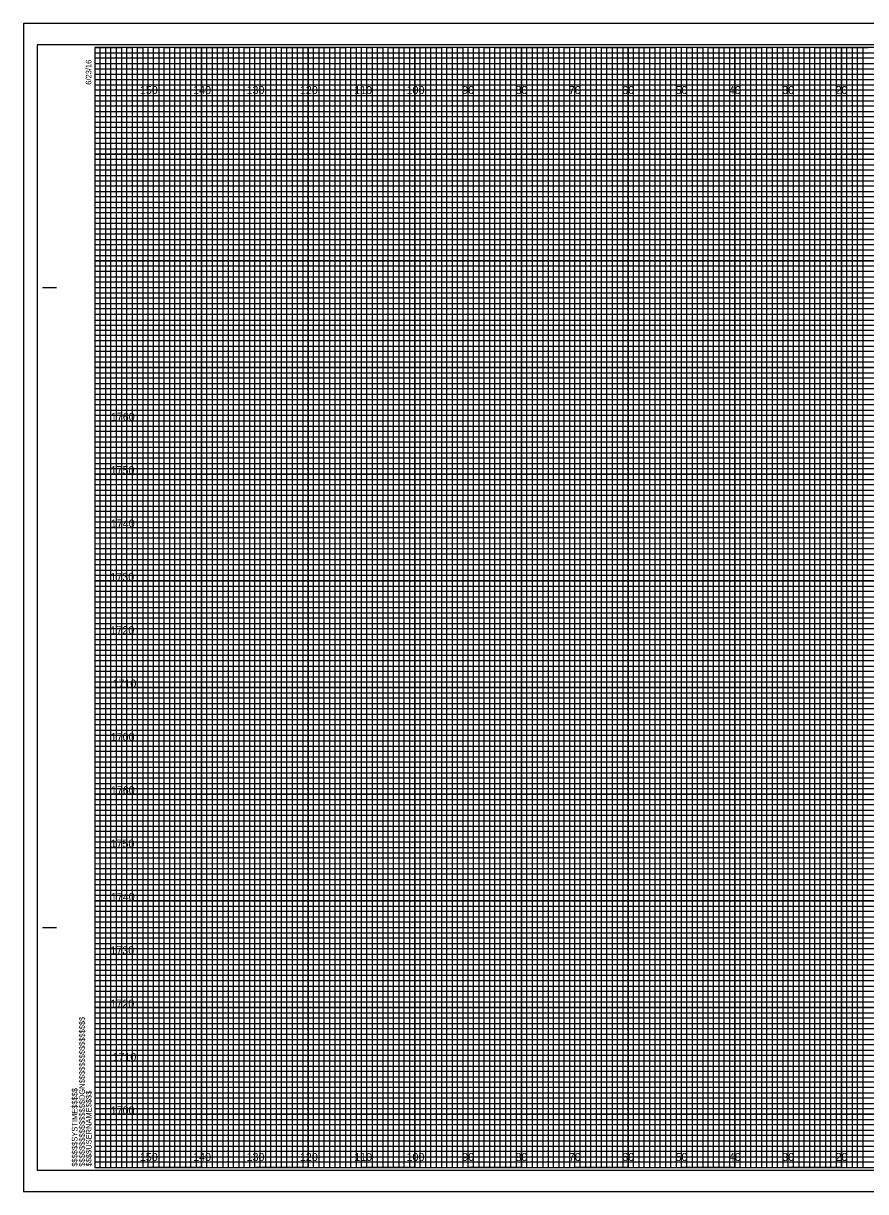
# Model space of a CAD drawing. Extents: x -419 to 4739, y -630 to 13534.
# Drawn here: x 476.2 to 634.1, y 5048 to 5267 of the extents above; entities that cross this region are included whole.
import ezdxf

# ---------------------------------------------------------------- set-up
doc = ezdxf.new("R2010")
doc.units = 0
for name, color, linetype in [('Old_Level_62', 7, 'Continuous'), ('Pattern 1', 7, 'Continuous'), ('Pattern 18', 7, 'Continuous'), ('Pattern 4', 7, 'Continuous'), ('Pattern 5', 7, 'Continuous'), ('Prop Dimension', 7, 'Continuous'), ('Prop Horizontal Alignment', 7, 'Continuous'), ('Raster_Level_0', 7, 'Continuous'), ('Scratch_Level_0', 7, 'Continuous'), ('Scratch_Level_3', 7, 'Continuous'), ('Scratch_Level_5', 7, 'Continuous')]:
    doc.layers.add(name, color=color, linetype=linetype)

msp = doc.modelspace()

# ---------------------------------------------------------------- linework, layer by layer
at = {"layer": 'Old_Level_62'}
for p, q in [((479.78, 5217.54), (482.28, 5217.54)), ((479.88, 5217.54), (482.38, 5217.54)), ((479.78, 5097.54), (482.28, 5097.54)), ((479.88, 5097.54), (482.38, 5097.54)), ((489.58, 5052.54), (489.58, 5052.54)), ((489.58, 5052.54), (489.58, 5052.54)), ((489.58, 5052.54), (489.58, 5052.54)), ((489.58, 5052.54), (489.58, 5052.54)), ((489.58, 5052.54), (489.58, 5052.54)), ((489.58, 5052.54), (489.58, 5052.54)), ((489.58, 5052.54), (489.58, 5052.54))]:
    msp.add_line(p, q, dxfattribs=at)
msp.add_lwpolyline([(809.58, 5262.54), (489.58, 5262.54), (489.58, 5052.54), (809.58, 5052.54)], close=True, dxfattribs=at)
at = {"layer": 'Pattern 18'}
msp.add_lwpolyline([(476.18, 5048.04), (812.88, 5048.04), (812.88, 5267.04), (476.18, 5267.04)], close=True, dxfattribs=at)
at = {"layer": 'Pattern 4'}
for p, q in [((489.58, 5261.54), (749.58, 5261.54)), ((749.58, 5260.52), (489.58, 5260.52)), ((489.58, 5260.52), (489.58, 5259.54)), ((489.58, 5259.54), (749.58, 5259.54)), ((749.58, 5258.43), (489.58, 5258.43)), ((489.58, 5258.43), (489.58, 5256.54)), ((489.58, 5256.54), (809.58, 5256.54))]:
    msp.add_line(p, q, dxfattribs=at)
for points in [[(489.58, 5255.54), (759.58, 5255.54), (809.58, 5255.54), (809.58, 5254.54), (489.58, 5254.54)], [(489.58, 5253.54), (809.58, 5253.54), (809.58, 5251.54), (489.58, 5251.54)], [(489.58, 5250.54), (809.58, 5250.54), (809.58, 5249.54), (489.58, 5249.52)], [(489.58, 5248.54), (809.58, 5248.54), (809.58, 5246.54), (489.58, 5246.54)], [(489.58, 5245.54), (809.58, 5245.54), (809.58, 5244.54), (489.58, 5244.54)], [(489.58, 5243.54), (809.58, 5243.54), (809.58, 5241.54), (489.58, 5241.54)], [(489.58, 5240.54), (809.58, 5240.54), (809.58, 5239.54), (489.58, 5239.54)], [(489.58, 5238.54), (809.58, 5238.54), (809.58, 5236.54), (489.58, 5236.54)], [(489.58, 5235.54), (809.58, 5235.54), (809.58, 5234.54), (489.58, 5234.54)], [(489.58, 5233.54), (809.58, 5233.54), (809.58, 5231.54), (489.58, 5231.54)], [(489.58, 5230.54), (809.58, 5230.54), (809.58, 5229.54), (489.58, 5229.54)], [(489.58, 5228.54), (809.58, 5228.54), (809.58, 5226.49), (809.58, 5225.54), (809.58, 5224.54), (489.58, 5224.54)], [(489.58, 5226.54), (809.58, 5226.54), (809.58, 5225.54), (489.58, 5225.54)], [(489.58, 5223.54), (809.58, 5223.54), (809.58, 5221.54), (489.58, 5221.57)], [(489.58, 5221.57), (809.58, 5221.54), (809.58, 5220.54), (489.58, 5220.54)], [(489.58, 5219.54), (809.58, 5219.54), (809.58, 5218.54), (489.58, 5218.54)], [(489.58, 5216.54), (809.58, 5216.54), (809.58, 5215.54), (489.58, 5215.54)], [(489.58, 5214.54), (809.58, 5214.54), (809.58, 5213.54), (489.58, 5213.54)], [(489.51, 5211.43), (809.58, 5211.43), (809.58, 5210.42), (489.51, 5210.42)], [(489.58, 5209.54), (809.58, 5209.54), (809.58, 5208.54), (489.58, 5208.54)], [(489.58, 5206.54), (809.58, 5206.54), (809.58, 5205.54), (489.58, 5205.54)], [(489.58, 5204.54), (809.58, 5204.54), (809.58, 5203.54), (489.58, 5203.54)], [(489.58, 5201.54), (809.58, 5201.54), (809.58, 5200.54), (489.58, 5200.54)], [(489.58, 5199.54), (809.58, 5199.54), (809.58, 5198.54), (489.58, 5198.54)], [(489.58, 5196.54), (809.58, 5196.54), (809.58, 5195.54), (489.58, 5195.54)], [(489.58, 5194.54), (809.58, 5194.54), (809.58, 5193.54), (489.58, 5193.54)], [(489.58, 5191.54), (809.58, 5191.54), (809.57, 5190.52), (489.58, 5190.54)], [(489.58, 5189.54), (809.58, 5189.54), (809.58, 5188.54), (489.58, 5188.54)], [(489.58, 5186.54), (809.58, 5186.54), (809.58, 5185.54), (489.58, 5185.54)], [(489.58, 5184.54), (809.58, 5184.54), (809.58, 5183.54), (489.58, 5183.54)], [(489.58, 5181.54), (809.58, 5181.54), (809.58, 5180.54), (489.58, 5180.54)], [(489.58, 5179.54), (809.58, 5179.54), (809.58, 5178.54), (489.58, 5178.54)], [(489.58, 5176.54), (809.58, 5176.54), (809.58, 5175.54), (489.58, 5175.54)], [(489.58, 5174.54), (809.58, 5174.54), (809.58, 5173.54), (489.58, 5173.54)], [(489.58, 5171.54), (809.58, 5171.54), (809.58, 5170.54), (489.58, 5170.54)], [(489.58, 5169.53), (809.65, 5169.45), (809.58, 5168.54), (489.58, 5168.54)], [(489.58, 5166.54), (809.58, 5166.54), (809.58, 5165.54), (489.58, 5165.54)], [(489.58, 5164.54), (809.58, 5164.54), (809.58, 5163.54), (489.58, 5163.54)], [(489.58, 5161.54), (809.58, 5161.54), (809.58, 5160.54), (489.58, 5160.54)], [(489.58, 5159.54), (809.58, 5159.54), (809.58, 5158.54), (489.58, 5158.54)], [(489.58, 5156.54), (809.58, 5156.54), (809.58, 5155.54), (489.58, 5155.54)], [(489.58, 5154.54), (809.58, 5154.54), (809.58, 5153.54), (489.58, 5153.54)], [(489.58, 5151.54), (809.58, 5151.54), (809.58, 5150.54), (489.58, 5150.54)], [(489.58, 5149.54), (809.58, 5149.54), (809.58, 5148.54), (489.58, 5148.54)], [(489.58, 5146.54), (809.58, 5146.54), (809.58, 5145.54), (489.58, 5145.54)], [(489.58, 5144.54), (809.58, 5144.54), (809.58, 5143.54), (489.58, 5143.54)], [(489.58, 5141.54), (809.58, 5141.54), (809.58, 5140.54), (489.58, 5140.54)], [(489.58, 5139.54), (809.58, 5139.54), (809.58, 5138.54), (489.58, 5138.54)], [(489.58, 5136.54), (809.58, 5136.54), (809.58, 5135.54), (489.58, 5135.54)], [(489.58, 5134.54), (809.58, 5134.54), (809.58, 5133.54), (489.58, 5133.54)], [(489.58, 5131.54), (809.58, 5131.54), (809.57, 5130.52), (489.58, 5130.54)], [(489.58, 5129.54), (809.58, 5129.54), (809.58, 5128.54), (489.58, 5128.54)], [(489.58, 5126.54), (809.58, 5126.54), (809.58, 5125.54), (489.58, 5125.54)], [(489.58, 5124.54), (809.58, 5124.54), (809.58, 5123.54), (489.58, 5123.54)], [(489.58, 5121.54), (809.58, 5121.54), (809.58, 5120.54), (489.58, 5120.54)], [(489.58, 5119.54), (809.58, 5119.54), (809.58, 5118.54), (489.58, 5118.54)], [(489.58, 5116.54), (809.58, 5116.54), (809.58, 5115.54), (489.58, 5115.54)], [(489.58, 5114.54), (809.58, 5114.54), (809.58, 5113.54), (489.58, 5113.54)], [(489.58, 5111.54), (809.58, 5111.54), (809.58, 5110.54), (489.58, 5110.54)], [(489.58, 5109.53), (809.65, 5109.45), (809.58, 5108.54), (489.58, 5108.54)], [(489.58, 5106.54), (809.58, 5106.54), (809.58, 5105.54), (489.58, 5105.54)], [(489.58, 5104.54), (809.58, 5104.54), (809.58, 5103.54), (489.58, 5103.54)], [(489.58, 5101.54), (809.58, 5101.54), (809.58, 5100.54), (489.58, 5100.54)], [(489.58, 5099.54), (809.58, 5099.54), (809.58, 5098.54), (489.58, 5098.54)], [(489.58, 5096.54), (809.58, 5096.54), (809.58, 5095.54), (489.58, 5095.54)], [(489.58, 5094.54), (809.58, 5094.54), (809.58, 5093.54), (489.58, 5093.54)], [(489.58, 5091.54), (809.58, 5091.54), (809.58, 5090.54), (489.58, 5090.54)], [(489.58, 5089.54), (809.58, 5089.54), (809.58, 5088.54), (489.58, 5088.54)], [(489.58, 5086.54), (809.58, 5086.54), (809.58, 5085.54), (489.58, 5085.54)], [(489.58, 5084.54), (809.58, 5084.54), (809.58, 5083.54), (489.58, 5083.54)], [(489.58, 5081.54), (809.58, 5081.54), (809.58, 5080.54), (489.58, 5080.54)], [(489.58, 5079.54), (809.58, 5079.54), (809.58, 5078.54), (489.58, 5078.54)], [(489.58, 5076.54), (809.58, 5076.54), (809.58, 5075.54), (489.58, 5075.54)], [(489.58, 5074.54), (809.58, 5074.54), (809.58, 5073.54), (489.58, 5073.54)], [(489.58, 5071.54), (809.58, 5071.54), (809.58, 5070.54), (489.58, 5070.54)], [(489.58, 5069.54), (809.58, 5069.54), (809.58, 5068.54), (489.58, 5068.54)], [(489.58, 5066.54), (809.58, 5066.54), (809.58, 5065.54), (489.58, 5065.54)], [(489.58, 5064.54), (809.58, 5064.54), (809.58, 5063.54), (489.58, 5063.54)], [(489.58, 5061.54), (809.58, 5061.54), (809.58, 5060.54), (489.58, 5060.54)], [(489.58, 5059.54), (809.58, 5059.54), (809.58, 5058.54), (489.58, 5058.54)], [(489.58, 5056.54), (809.58, 5056.54), (809.58, 5055.54), (489.58, 5055.54)], [(489.58, 5054.54), (809.58, 5054.54), (809.58, 5053.54), (489.58, 5053.54)]]:
    msp.add_lwpolyline(points, dxfattribs=at)
at = {"layer": 'Pattern 5'}
for p, q in [((812.88, 5267.04), (476.18, 5267.04)), ((476.18, 5267.04), (476.18, 5048.04)), ((476.18, 5048.04), (812.88, 5048.04))]:
    msp.add_line(p, q, dxfattribs=at)
at = {"layer": 'Prop Dimension'}
for points in [[(489.58, 5052.54), (490.58, 5052.54), (490.58, 5262.54), (491.58, 5262.54), (491.58, 5052.54)], [(491.58, 5052.54), (492.58, 5052.54), (492.58, 5262.54), (493.58, 5262.54), (493.58, 5052.54)], [(494.58, 5052.54), (495.58, 5052.54), (495.58, 5262.54), (496.58, 5262.54), (496.58, 5052.54)], [(496.58, 5052.54), (497.58, 5052.54), (497.58, 5262.54), (498.58, 5262.54), (498.58, 5052.54)], [(499.58, 5052.54), (500.58, 5052.54), (500.58, 5262.54), (501.58, 5262.54), (501.58, 5052.54)], [(501.58, 5052.54), (502.58, 5052.54), (502.58, 5262.54), (503.58, 5262.54), (503.58, 5052.54)], [(504.58, 5052.54), (505.58, 5052.54), (505.58, 5262.54), (506.58, 5262.54), (506.58, 5052.54)], [(506.58, 5052.54), (507.58, 5052.54), (507.58, 5262.54), (508.58, 5262.54), (508.58, 5052.54)], [(509.58, 5052.54), (510.58, 5052.54), (510.58, 5262.54), (511.58, 5262.54), (511.58, 5052.54)], [(511.58, 5052.54), (512.58, 5052.54), (512.58, 5262.54), (513.58, 5262.54), (513.58, 5052.54)], [(514.58, 5052.54), (515.58, 5052.54), (515.58, 5262.54), (516.58, 5262.54), (516.58, 5052.54)], [(516.58, 5052.54), (517.58, 5052.54), (517.58, 5262.54), (518.58, 5262.54), (518.58, 5052.54)], [(519.58, 5052.54), (520.58, 5052.54), (520.58, 5262.54), (521.58, 5262.54), (521.58, 5052.54)], [(521.58, 5052.54), (522.58, 5052.54), (522.58, 5262.54), (523.58, 5262.54), (523.58, 5052.54)], [(524.58, 5052.54), (525.58, 5052.54), (525.58, 5262.54), (526.58, 5262.54), (526.58, 5052.54)], [(526.58, 5052.54), (527.58, 5052.54), (527.58, 5262.54), (528.58, 5262.54), (528.58, 5052.54)], [(529.58, 5052.54), (530.58, 5052.54), (530.58, 5262.54), (531.58, 5262.54), (531.58, 5052.54)], [(531.58, 5052.54), (532.58, 5052.54), (532.58, 5262.54), (533.58, 5262.54), (533.58, 5052.54)], [(534.58, 5052.54), (535.58, 5052.54), (535.58, 5262.54), (536.58, 5262.54), (536.58, 5052.54)], [(536.58, 5052.54), (537.58, 5052.54), (537.58, 5262.54), (538.58, 5262.54), (538.58, 5052.54)], [(539.58, 5052.54), (540.58, 5052.54), (540.58, 5262.54), (541.58, 5262.54), (541.58, 5052.54)], [(541.58, 5052.54), (542.58, 5052.54), (542.58, 5262.54), (543.58, 5262.54), (543.58, 5052.54)], [(544.58, 5052.54), (545.58, 5052.54), (545.58, 5262.54), (546.58, 5262.54), (546.58, 5052.54)], [(546.58, 5052.54), (547.58, 5052.54), (547.58, 5262.54), (548.58, 5262.54), (548.58, 5052.54)], [(549.58, 5052.54), (550.58, 5052.54), (550.58, 5262.54), (551.58, 5262.54), (551.58, 5052.54)], [(551.58, 5052.54), (552.58, 5052.54), (552.58, 5262.54), (553.58, 5262.54), (553.58, 5052.54)], [(554.58, 5052.54), (555.58, 5052.54), (555.58, 5262.54), (556.58, 5262.54), (556.58, 5052.54)], [(556.58, 5052.54), (557.58, 5052.54), (557.58, 5262.54), (558.58, 5262.54), (558.58, 5052.54)], [(559.58, 5052.54), (560.58, 5052.54), (560.58, 5262.54), (561.58, 5262.54), (561.58, 5052.54)], [(561.58, 5052.54), (562.58, 5052.54), (562.58, 5262.54), (563.58, 5262.54), (563.58, 5052.54)], [(564.58, 5052.54), (565.58, 5052.54), (565.58, 5262.54), (566.58, 5262.54), (566.58, 5052.54)], [(566.58, 5052.54), (567.58, 5052.54), (567.58, 5262.54), (568.58, 5262.54), (568.58, 5052.54)], [(569.58, 5052.54), (570.58, 5052.54), (570.58, 5262.54), (571.58, 5262.54), (571.58, 5052.54)], [(571.58, 5052.54), (572.58, 5052.54), (572.58, 5262.54), (573.58, 5262.54), (573.58, 5052.54)], [(574.58, 5052.54), (575.58, 5052.54), (575.58, 5262.54), (576.58, 5262.54), (576.58, 5052.54)], [(576.58, 5052.54), (577.58, 5052.54), (577.58, 5262.54), (578.58, 5262.54), (578.58, 5052.54)], [(579.58, 5052.54), (580.58, 5052.54), (580.58, 5262.54), (581.58, 5262.54), (581.58, 5052.54)], [(581.58, 5052.54), (582.58, 5052.54), (582.58, 5262.54), (583.58, 5262.54), (583.58, 5052.54)], [(584.58, 5052.54), (585.58, 5052.54), (585.58, 5262.54), (586.58, 5262.54), (586.58, 5052.54)], [(586.58, 5052.54), (587.58, 5052.54), (587.58, 5262.54), (588.58, 5262.54), (588.58, 5052.54)], [(589.58, 5052.54), (590.58, 5052.54), (590.58, 5262.54), (591.58, 5262.54), (591.58, 5052.54)], [(591.58, 5052.54), (592.58, 5052.54), (592.58, 5262.54), (593.58, 5262.54), (593.58, 5052.54)], [(594.58, 5052.54), (595.58, 5052.54), (595.58, 5262.54), (596.58, 5262.54), (596.58, 5052.54)], [(596.58, 5052.54), (597.58, 5052.54), (597.58, 5262.54), (598.58, 5262.54), (598.58, 5052.54)], [(599.58, 5052.54), (600.58, 5052.54), (600.58, 5262.54), (601.58, 5262.54), (601.58, 5052.54)], [(601.58, 5052.54), (602.58, 5052.54), (602.58, 5262.54), (603.58, 5262.54), (603.58, 5052.54)], [(604.58, 5052.54), (605.58, 5052.54), (605.58, 5262.54), (606.58, 5262.54), (606.58, 5052.54)], [(606.58, 5052.54), (607.58, 5052.54), (607.58, 5262.54), (608.58, 5262.54), (608.58, 5052.54)], [(609.58, 5052.54), (610.58, 5052.54), (610.58, 5262.54), (611.58, 5262.54), (611.58, 5052.54)], [(611.58, 5052.54), (612.58, 5052.54), (612.58, 5262.54), (613.58, 5262.54), (613.58, 5052.54)], [(614.58, 5052.54), (615.58, 5052.54), (615.58, 5262.54), (616.58, 5262.54), (616.58, 5052.54)], [(616.58, 5052.54), (617.58, 5052.54), (617.58, 5262.54), (618.58, 5262.54), (618.58, 5052.54)], [(619.58, 5052.54), (620.58, 5052.54), (620.58, 5262.54), (621.58, 5262.54), (621.58, 5052.54)], [(621.58, 5052.54), (622.58, 5052.54), (622.58, 5262.54), (623.58, 5262.54), (623.58, 5052.54)], [(624.58, 5052.54), (625.58, 5052.54), (625.58, 5262.54), (626.58, 5262.54), (626.58, 5052.54)], [(626.58, 5052.54), (627.58, 5052.54), (627.58, 5262.54), (628.58, 5262.54), (628.58, 5052.54)], [(629.58, 5052.54), (630.58, 5052.54), (630.58, 5262.54), (631.58, 5262.54), (631.58, 5052.54)], [(631.58, 5052.54), (632.58, 5052.54), (632.58, 5262.54), (633.58, 5262.54), (633.58, 5052.54)]]:
    msp.add_lwpolyline(points, dxfattribs=at)
at = {"layer": 'Prop Horizontal Alignment'}
for points in [[(489.58, 5262.54), (494.58, 5262.54), (494.58, 5052.54), (504.58, 5052.54), (504.58, 5262.54), (514.58, 5262.54), (514.58, 5052.54), (524.58, 5052.54), (524.58, 5262.54), (534.58, 5262.54), (534.58, 5052.54), (544.58, 5052.54), (544.58, 5262.54), (554.58, 5262.54), (554.58, 5052.54), (564.58, 5052.54), (564.58, 5262.54), (574.58, 5262.54), (574.58, 5052.54), (584.58, 5052.54), (584.58, 5262.54), (594.58, 5262.54), (594.58, 5052.54), (604.58, 5052.54), (604.58, 5262.54), (614.58, 5262.54), (614.58, 5052.54), (624.58, 5052.54), (624.58, 5262.54), (634.58, 5262.54)], [(489.58, 5257.54), (764.58, 5257.54)], [(489.58, 5237.54), (809.58, 5237.54), (809.58, 5247.54), (489.58, 5247.54)], [(489.58, 5217.54), (809.58, 5217.54), (809.58, 5227.54), (489.58, 5227.54)], [(489.58, 5197.54), (809.58, 5197.54), (809.58, 5207.54), (489.58, 5207.54)], [(489.58, 5177.54), (809.58, 5177.54), (809.58, 5187.54), (489.58, 5187.54)], [(489.58, 5157.54), (809.58, 5157.54), (809.58, 5167.54), (489.58, 5167.54)], [(489.58, 5137.54), (809.58, 5137.54), (809.58, 5147.54), (489.58, 5147.54)], [(489.58, 5117.54), (809.58, 5117.54), (809.58, 5127.54), (489.58, 5127.54)], [(489.58, 5097.54), (809.58, 5097.54), (809.58, 5107.54), (489.58, 5107.54)], [(489.58, 5077.54), (809.58, 5077.54), (809.58, 5087.54), (489.58, 5087.54)], [(489.58, 5057.54), (809.58, 5057.54), (809.58, 5067.54), (489.58, 5067.54)]]:
    msp.add_lwpolyline(points, dxfattribs=at)
at = {"layer": 'Scratch_Level_0'}
for p, q in [((499.58, 5052.54), (499.58, 5262.54)), ((509.58, 5052.54), (509.58, 5262.54)), ((519.58, 5052.54), (519.58, 5262.54)), ((529.58, 5052.54), (529.58, 5262.54)), ((539.58, 5052.54), (539.58, 5262.54)), ((549.58, 5052.54), (549.58, 5262.54)), ((559.58, 5052.54), (559.58, 5262.54)), ((569.58, 5052.54), (569.58, 5262.54)), ((579.58, 5052.54), (579.58, 5262.54)), ((589.58, 5052.54), (589.58, 5262.54)), ((599.58, 5052.54), (599.58, 5262.54)), ((609.58, 5052.54), (609.58, 5262.54)), ((619.58, 5052.54), (619.58, 5262.54)), ((629.58, 5052.54), (629.58, 5262.54)), ((489.58, 5252.54), (809.58, 5252.54)), ((489.58, 5242.54), (809.58, 5242.54)), ((489.58, 5232.54), (809.58, 5232.54)), ((489.58, 5222.54), (809.58, 5222.54)), ((489.58, 5212.54), (809.58, 5212.54)), ((489.58, 5202.54), (809.58, 5202.54)), ((489.58, 5192.54), (809.58, 5192.54)), ((489.58, 5182.54), (809.58, 5182.54)), ((489.58, 5172.54), (809.58, 5172.54)), ((489.58, 5162.54), (809.58, 5162.54)), ((489.58, 5152.54), (809.58, 5152.54)), ((489.58, 5142.54), (809.58, 5142.54)), ((489.58, 5132.54), (809.58, 5132.54)), ((489.58, 5122.54), (809.58, 5122.54)), ((489.58, 5112.54), (809.58, 5112.54)), ((489.58, 5102.54), (809.58, 5102.54)), ((489.58, 5092.54), (809.58, 5092.54)), ((489.58, 5082.54), (809.58, 5082.54)), ((489.58, 5072.54), (809.58, 5072.54)), ((489.58, 5062.54), (809.58, 5062.54))]:
    msp.add_line(p, q, dxfattribs=at)
at = {"layer": 'Scratch_Level_3'}
for p, q in [((499.58, 5262.54), (489.58, 5262.54)), ((499.58, 5052.54), (499.58, 5262.54)), ((519.58, 5262.54), (509.58, 5262.54)), ((509.58, 5262.54), (509.58, 5052.54)), ((519.58, 5052.54), (519.58, 5262.54)), ((539.58, 5262.54), (529.58, 5262.54)), ((529.58, 5262.54), (529.58, 5052.54)), ((539.58, 5052.54), (539.58, 5262.54)), ((559.58, 5262.54), (549.58, 5262.54)), ((549.58, 5262.54), (549.58, 5052.54)), ((559.58, 5052.54), (559.58, 5262.54)), ((579.58, 5262.54), (569.58, 5262.54)), ((569.58, 5262.54), (569.58, 5052.54)), ((579.58, 5052.54), (579.58, 5262.54)), ((599.58, 5262.54), (589.58, 5262.54)), ((589.58, 5262.54), (589.58, 5052.54)), ((599.58, 5052.54), (599.58, 5262.54)), ((619.58, 5262.54), (609.58, 5262.54)), ((609.58, 5262.54), (609.58, 5052.54)), ((619.58, 5052.54), (619.58, 5262.54)), ((639.58, 5262.54), (629.58, 5262.54)), ((629.58, 5262.54), (629.58, 5052.54)), ((509.58, 5052.54), (499.58, 5052.54)), ((529.58, 5052.54), (519.58, 5052.54)), ((549.58, 5052.54), (539.58, 5052.54)), ((569.58, 5052.54), (559.58, 5052.54)), ((589.58, 5052.54), (579.58, 5052.54)), ((609.58, 5052.54), (599.58, 5052.54)), ((629.58, 5052.54), (619.58, 5052.54))]:
    msp.add_line(p, q, dxfattribs=at)
for points in [[(489.58, 5252.54), (809.58, 5252.54), (809.58, 5242.54), (489.58, 5242.54)], [(489.58, 5232.54), (809.58, 5232.54), (809.58, 5222.54), (489.58, 5222.54)], [(489.58, 5212.54), (809.58, 5212.54), (809.58, 5202.54), (489.58, 5202.54)], [(489.58, 5192.54), (809.58, 5192.54), (809.58, 5182.54), (489.58, 5182.54)], [(489.58, 5172.54), (809.58, 5172.54), (809.58, 5162.54), (489.58, 5162.54)], [(489.58, 5152.54), (809.58, 5152.54), (809.58, 5142.54), (489.58, 5142.54)], [(489.58, 5132.54), (809.58, 5132.54), (809.58, 5122.54), (489.58, 5122.54)], [(489.58, 5112.54), (809.58, 5112.54), (809.58, 5102.54), (489.58, 5102.54)], [(489.58, 5092.54), (809.58, 5092.54), (809.58, 5082.54), (489.58, 5082.54)], [(489.58, 5072.54), (809.58, 5072.54), (809.58, 5062.54), (489.58, 5062.54)]]:
    msp.add_lwpolyline(points, dxfattribs=at)
at = {"layer": 'Scratch_Level_5'}
msp.add_lwpolyline([(478.78, 5052.04), (811.98, 5052.04), (811.98, 5263.04), (478.78, 5263.04)], close=True, dxfattribs=at)

# ---------------------------------------------------------------- texts
at = {"layer": 'Old_Level_62'}
for s, p in [('6/23/16', (488.93, 5255.54)), ('$$$$$$$$$$$$$$$$DGN$$$$$$$$$$$$$$$$', (487.7, 5052.72)), ('$$$$$$SYSTIME$$$$$', (486.32, 5052.72)), ('$$$$USERNAME$$$$', (488.96, 5052.77))]:
    msp.add_text(s, height=1.05, rotation=90, dxfattribs=at).set_placement(p)
at = {"layer": 'Pattern 1'}
for s, p in [('1760', (492.58, 5192.54)), ('1750', (492.53, 5182.54)), ('1740', (492.58, 5172.54)), ('1730', (492.5, 5162.54)), ('1720', (492.51, 5152.54)), ('1710', (492.89, 5142.54)), ('1700', (492.56, 5132.54)), ('1760', (492.58, 5122.54)), ('1750', (492.53, 5112.54)), ('1740', (492.58, 5102.54)), ('1730', (492.5, 5092.54)), ('1720', (492.51, 5082.54)), ('1710', (492.89, 5072.54)), ('1700', (492.56, 5062.54))]:
    msp.add_text(s, height=1.5, dxfattribs=at).set_placement(p)
at = {"layer": 'Raster_Level_0'}
for s, p in [('150', (498.02, 5253.79)), ('140', (508.02, 5253.79)), ('130', (518.02, 5253.79)), ('120', (528.02, 5253.79)), ('110', (538.2, 5253.79)), ('100', (548.02, 5253.79)), ('90', (558.44, 5253.79)), ('80', (568.44, 5253.79)), ('70', (578.44, 5253.79)), ('60', (588.44, 5253.79)), ('50', (598.44, 5253.79)), ('40', (608.44, 5253.79)), ('30', (618.44, 5253.79)), ('20', (628.44, 5253.79)), ('150', (498.02, 5053.79)), ('140', (508.02, 5053.79)), ('130', (518.02, 5053.79)), ('120', (528.02, 5053.79)), ('110', (538.2, 5053.79)), ('100', (548.02, 5053.79)), ('90', (558.44, 5053.79)), ('80', (568.44, 5053.79)), ('70', (578.44, 5053.79)), ('60', (588.44, 5053.79)), ('50', (598.44, 5053.79)), ('40', (608.44, 5053.79)), ('30', (618.44, 5053.79)), ('20', (628.44, 5053.79))]:
    msp.add_text(s, height=1.5, dxfattribs=at).set_placement(p)

doc.saveas('drawing.dxf')
